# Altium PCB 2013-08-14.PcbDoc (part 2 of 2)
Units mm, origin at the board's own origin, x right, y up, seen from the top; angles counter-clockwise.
Board outline 30.96 x 91.67 mm, 2 copper layers (Top Layer, Bottom Layer); 88 components, 66 nets, 245 pads, 39 vias.
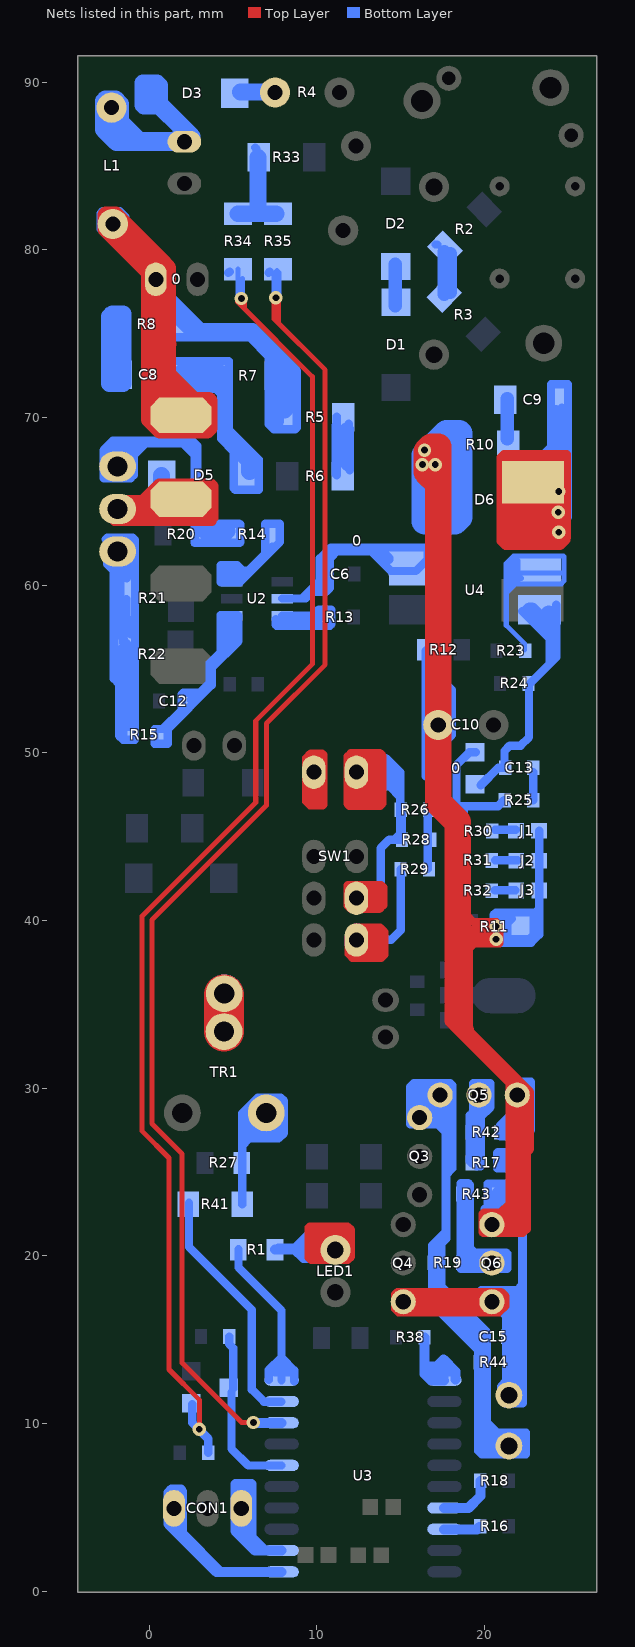
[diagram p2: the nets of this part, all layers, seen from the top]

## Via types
v1: diameter 0.8, hole 0.4, Top Layer to Bottom Layer, 36 vias
v2: diameter 1.27, hole 0.8, Top Layer to Bottom Layer, 3 vias

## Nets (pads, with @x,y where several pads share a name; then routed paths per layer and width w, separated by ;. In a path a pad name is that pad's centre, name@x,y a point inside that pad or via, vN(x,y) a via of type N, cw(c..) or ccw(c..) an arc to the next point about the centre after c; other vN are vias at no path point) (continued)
NewNet16: C15.1 pad.1@21.463,8.661 Q3.C Q5.C R19.1 R44.1 | length 80.4
  Bottom Layer w0.5: 17.95,30.308 18.079,30.179 18.079,25.209 17.723,24.853 17.723,21.028 17.432,20.737 17.432,18.171 20.149,15.454 20.149,10.065 20.224,9.99 20.753,9.461 22.477,9.461 22.477,8.157 19.847,8.157 19.642,8.362 19.642,14.355 16.893,17.104 16.893,20.639 17.68,21.426 17.68,27.398 17.228,27.85 15.568,27.85 15.568,30.083 15.793,30.308 17.96,30.308
  Bottom Layer w1: 16.57,29.252 16.57,28.616 16.85,28.336 16.375,28.336 16.171,28.54 16.171,29.597 16.085,29.683 Q5.C@17.303,29.683 ; 17.179,20.413 17.179,17.605 19.895,14.889 19.895,9.661 20.666,8.89 pad.1@21.464,8.89 ; Q5.C@17.411,29.759 17.411,28.324 17.82,27.915 ; 20.106,9.559 20.106,8.76 20.407,8.459 pad.1@22.024,8.459 ; 20.537,9.149 pad.1@22.089,9.149
NewNet17: Q6.B R19.2 R43.1 | length 23.3
  Bottom Layer w0.5: R43.1@18.731,24.013 18.731,19.896 19.087,19.54 Q6.B@20.407,19.54 ; 18.931,20.435 18.931,20.17 19.362,19.739 Q6.B@20.359,19.739 ; R19.2@18.585,19.222 18.585,24.331 19.038,24.331 19.135,24.234 19.135,20.478 19.421,20.192 21.308,20.192 21.356,20.144 21.356,19.222 R19.2@18.585,19.222
NewNet18: C15.2 pad.2 Q4.C Q6.C R17.2 R44.2 | length 67.4
  Top Layer w0.5: Q4.C@14.687,16.83 14.877,16.64 20.873,16.64 21.241,17.008 21.241,17.6 21.004,17.837 14.817,17.837 14.687,17.707 Q4.C@14.687,16.83
  Top Layer w1: Q4.C@15.291,17.268 Q6.C@20.649,17.268
  Bottom Layer w0.5: 20.764,26.149 20.764,25.231 21.863,25.231 22.24,24.854 22.24,18.246 21.939,17.945 19.805,17.945 19.696,17.836 19.696,17.093 20.019,16.77 20.935,16.77 21.302,16.403 21.302,12.522 20.989,12.209 20.989,11.478 21.25,11.217 22.282,11.217 22.282,26.17 20.785,26.17 R17.2@20.785,25.544
  Bottom Layer w1: Q6.C@20.612,17.557 21.658,16.511 21.658,16.403 ; Q6.C@20.725,17.4 21.814,17.4 21.776,17.362 pad.2@21.776,11.542 ; 21.415,25.679 21.954,25.679
NewNet19: Q5.B R17.1 R42.1 | length 16.6
  Bottom Layer w0.5: R17.1@19.253,25.527 19.135,25.645 19.135,28.384 19.329,28.578 19.329,30.287 20.353,30.287 20.353,28.859 19.771,28.277 19.771,25.43 19.771,25.35 R17.1@19.534,25.35 ; R17.1@19.367,25.646 19.367,28.266 19.895,28.794 Q5.B@19.895,30.034 ; Q5.B@19.588,28.918 Q5.B@19.588,29.602
NewNet20: R38.2 U3.11 | length 13.6
  Bottom Layer w0.254: U3.11@16.721,12.554 16.721,12.665 17.605,13.549 U3.11@18.489,12.665 ; 17.163,12.925 18.126,12.925 ; 17.226,13.044 18.039,13.044 ; 17.371,13.234 17.783,13.234 17.832,13.185
  Bottom Layer w0.6: R38.2@16.434,15.138 16.434,12.956 16.817,12.573 U3.11@17.602,12.573 ; 16.483,13.386 17.321,13.386 17.369,13.338 ; 16.51,13.512 16.636,13.386 16.832,13.386 ; 16.591,12.799 16.591,12.84 17.567,13.816 ; U3.11@17.567,12.732 17.567,13.816 ; U3.11@18.276,12.623 18.276,13.107 17.567,13.816
NewNet21: R16.1 U3.18 | length 2.2
  Bottom Layer w0.6: U3.18@17.602,3.683 19.549,3.683 R16.1@19.706,3.84
NewNet22: R18.1 U3.17 | length 3.4
  Bottom Layer w0.6: U3.17@17.602,4.953 19.041,4.953 19.761,5.673 R18.1@19.761,6.579
NewNet23: CON1.1 U3.2 | length 15.3
  Bottom Layer w0.6: CON1.1@5.304,5.933 5.863,5.933 ; 5.467,3.727 CON1.1@5.467,4.859 ; 5.802,3.296 CON1.1@5.802,5.645 ; U3.2@6.91,2.413 6.093,3.23 6.093,6.378 5.144,6.378 5.144,3.587 6.318,2.413 U3.2@7.899,2.413
NewNet24: CON1.3 U3.1 | length 20
  Bottom Layer w0.6: 1.889,6.055 1.328,6.055 1.156,5.883 1.156,3.996 4.009,1.143 7.899,1.143 4.257,1.143 1.975,3.425 1.975,5.947
NewNet25: pad.89 pad.138 U3.6 | length 10
  Bottom Layer w0.5: pad.138@4.775,15.189 4.775,14.746 5.015,14.506 pad.89@5.015,12.087 ; pad.89@4.918,11.854 4.918,8.491 5.916,7.493 U3.6@7.899,7.493
NewNet26: LED1.K R1.2 | length 28.1
  Top Layer w0.5: 9.721,21.749 11.836,21.749 12.026,21.559 12.026,19.941 11.842,19.757 9.662,19.757 9.525,19.894 9.525,21.689 9.585,21.749 9.949,21.749
  Top Layer w1: 10.088,21.298 10.088,20.255 10.147,20.196 11.404,20.196 11.582,20.374 11.582,21.262 11.534,21.31 10.609,21.31 ; LED1.K@10.657,20.682 LED1.K@11.155,20.682
  Bottom Layer w0.6: R1.2@7.518,20.371 8.711,20.371 9.208,19.874 11.773,19.874 11.913,20.014 11.913,20.941 11.589,21.265 9.531,21.265 8.711,20.445 R1.2@7.731,20.445 ; 9.175,20.467 LED1.K@11.601,20.467 ; 9.574,20.79 LED1.K@11.127,20.79
NewNet27: R1.1 U3.10 | length 18.8
  Bottom Layer w0.254: U3.10@7.018,12.554 7.018,12.665 7.941,13.588 7.941,13.478 ; U3.10@7.064,12.52 7.064,13.005 7.766,13.707 7.899,13.707 ; 7.46,12.925 8.423,12.925 ; 7.523,13.044 8.336,13.044 ; 7.863,13.588 U3.10@8.786,12.665
  Bottom Layer w0.5: R1.1@5.333,20.402 5.333,19.308 7.899,16.742 U3.10@7.899,12.573 ; U3.10@7.137,12.592 7.137,13.19 7.888,13.941 7.899,13.941 ; 7.899,13.799 7.899,14.103 ; 7.899,13.868 7.953,13.868 8.655,13.166 U3.10@8.655,12.512
NewNet28: R27.2 R41.1 TR1.G | length 18.1
  Bottom Layer w0.5: R41.1@5.563,23.063 5.563,28.506 6.491,29.435 7.85,29.435 8.033,29.252 8.033,27.312 7.72,26.999 5.963,26.999 5.563,26.598
  Bottom Layer w1: TR1.G@7.289,28.648 6.308,28.648 5.942,28.282 5.942,27.484 5.964,27.506 6.934,27.506 7.58,28.152 7.58,27.711 7.332,27.463
NewNet29: R41.2 U3.9 | length 14.7
  Bottom Layer w0.5: R41.2@2.379,23.162 2.379,20.526 6.13,16.775 6.13,12.022 6.847,11.305 U3.9@7.871,11.305
NewNet30: pad.252 R14.2 R20.1 | length 38.2
  Bottom Layer w0.5: pad.252@-2.494,67.833 -2.164,68.163 -0.868,68.163 ; pad.252@-1.92,67.043 -0.498,68.465 2.644,68.465 2.87,68.239 2.87,64.149 3.349,63.67 R14.2@5.381,63.67 ; pad.252@-1.656,66.385 -1.097,66.385 -0.919,66.563 -0.919,67.754 -0.208,68.465 ; pad.252@-1.427,66.385 -2.697,66.385 -2.722,66.41 -2.722,68.061 -2.164,68.62 2.561,68.62 2.87,68.311 2.87,67.782 ; 2.129,68.341 2.729,67.74 2.729,67.325 ; 2.729,67.875 2.729,62.543 2.745,62.527 5.403,62.527 5.435,62.559 R14.2@5.435,63.648
  Bottom Layer w1: R20.1@3.344,63.217 R14.2@4.648,63.217
NewNet31: R5.2 R6.2 | length 12
  Bottom Layer w0.5: R5.2@11.143,69.539 11.143,66.618 11.191,66.57 R5.2@11.191,70.062 ; R5.2@11.671,69.432 11.671,67.173 11.978,66.866 11.978,69.345 11.913,69.41 R5.2@11.913,69.625
NewNet32: C9.1 R10.2 | length 2.4
  Bottom Layer w0.8: R10.2@21.357,68.722 C9.1@21.357,71.135
NewNet33: 0.3@1.902,65.131 D5.1 pad.33 pad.251 | length 31.1
  Top Layer w0.5: pad.251@-2.327,64.045 -2.073,63.791 3.769,63.791 ; pad.251@-2.2,65.138 -0.422,65.138 0.566,66.125 3.712,66.125 3.901,65.936 3.901,64.003 3.748,63.85
  Top Layer w1: pad.251@-1.336,64.147 3.566,64.147 ; pad.251@-1.158,64.604 -0.93,64.833 0.3@1.814,64.833 ; 0.3@0.405,65.45 3.309,65.45 3.451,65.592 3.451,64.537 0.3@3.38,64.466
  Bottom Layer w1: pad.251@-2.073,64.884 -0.244,64.884 0.747,65.875 D5.1@0.747,66.56
NewNet34: D1.2 D2.2 | length 2.5
  Bottom Layer w0.8: D1.2@14.677,76.672 D2.2@14.677,79.136
NewNet35: D3.1 R4.1 | length 2.1
  Bottom Layer w1: D3.1@5.431,89.423 R4.1@7.488,89.423
NewNet36: R35.1 U3.8 | length 84.4
  Top Layer w0.3: v1@6.147,10.062 5.525,10.062 1.976,13.611 1.976,26.08 0.173,27.883 0.173,40.045 7.001,46.873 7.001,51.764 10.5,55.264 10.5,72.847 7.565,75.783 v1(7.565,77.154) ; v1@7.463,77.053 7.463,75.884 7.641,75.707 ; 7.717,75.707 v1@7.717,77.154
  Bottom Layer w0.3: R35.1@7.336,78.602 7.463,78.475 v1@7.463,77.154 ; v1(7.565,77.154) 7.565,78.704 R35.1@7.641,78.78 ; v1@7.742,77.231 R35.1@7.742,78.653
  Bottom Layer w0.6: v1@6.346,10.033 U3.8@7.899,10.033
  other v1: 6.223,10.058
NewNet37: pad.91 pad.140 R34.1 | length 82
  Top Layer w0.3: v1(2.997,9.652) 2.997,11.411 1.187,13.221 1.187,25.838 -0.413,27.438 -0.413,40.272 6.361,47.046 6.361,51.915 9.736,55.29 9.736,72.443 5.507,76.672 ; v1@5.279,77.104 5.279,76.9 5.507,76.672 ; v1(5.507,77.104) 5.507,76.672 ; 5.685,76.545 v1@5.685,76.926
  Bottom Layer w0.3: R34.1@5.304,78.856 5.304,77.332 5.533,77.104 v1@5.533,77.053 ; R34.1@5.583,78.297 5.583,77.256 v1@5.609,77.231
  Bottom Layer w0.5: pad.91@2.579,11.143 2.579,10.043 3.531,9.092 pad.140@3.531,8.255
NewNet38: R33.1 R34.2 R35.2 | length 5.4
  Bottom Layer w1: R34.2@5.304,82.158 R35.2@7.59,82.158 ; 6.498,82.387 R33.1@6.498,85.511
NewNet39: R2.1 R3.2 | length 4.8
  Bottom Layer w0.8: R3.2@17.598,77.358 R2.1@17.598,79.898 ; R3.2@17.979,77.485 R2.1@17.979,79.771
NewNet41: C8.1 R8.1 | length 9.8
  Bottom Layer w1: R8.1@-1.571,76.195 -2.199,76.195 -2.37,76.024 -2.37,72.035 -1.539,72.035 R8.1@-1.539,76.195
NewNet42: C8.2 D5.2 pad.32 R7.1 | length 32.5
  Bottom Layer w0.5: C8.2@1.145,71.722 3.959,71.722 4.287,71.394 4.287,68.747 5.042,67.992 5.042,65.787 5.133,65.696 6.529,65.696 6.529,67.502 4.74,69.291 4.74,73.376 1.145,73.376 C8.2@1.145,71.722
  Bottom Layer w1: C8.2@2.029,72.768 4.109,72.768 3.559,72.218 C8.2@2.244,72.218 ; 3.43,72.52 3.818,72.52 R7.1@4.497,71.841 ; 4.605,68.801 5.996,67.41 pad.32@5.996,66.764
NewNet43: 0.1@0.402,78.247 0.1@1.902,70.135 L1.1 R5.1 R7.2 R8.2 | length 143.9
  Top Layer w0.5: -0.176,69.782 0.387,69.219 3.588,69.219 3.824,69.455 3.824,70.973 ; -0.176,71.782 -0.176,79.74
  Top Layer w1: L1.1@-2.164,81.549 0.381,79.004 0.381,71.989 ; -0.081,79.161 0.021,79.059 0.021,69.89 0.656,69.255 3.45,69.255 3.577,69.382 3.577,71.008 ; 0.1@0.326,77.688 0.326,78.348 -2.57,81.244 -2.57,82.082 -2.011,82.082 0.91,79.161 ; 0.1@0.381,69.989 1.116,70.724 1.981,70.724 0.962,71.743 ; 0.58,71.465 0.63,71.414 0.1@0.63,70.627 ; 0.862,79.209 0.862,79.184 1.113,78.932 1.113,72.582 2.662,71.033 3.551,71.033 ; 0.962,73.743 0.962,74.537 1.128,74.371 ; 1.021,75.023 0.1@1.021,78.364 ; 0.1@1.128,70.866 1.128,72.371 ; 0.1@3.38,69.953 0.1@3.38,70.664
  Bottom Layer w0.5: L1.1@-2.214,81.549 -2.214,80.731 3.118,75.398 6.211,75.398 8.809,72.8 8.809,69.397 8.719,69.307 7.435,69.307 7.138,69.604 7.138,73.652 6.007,74.783 1.107,74.783 1.075,74.815 1.075,76.713 0.762,77.026 0.1@0.762,78.201 ; L1.1@-2.113,81.193 0.097,78.983 0.1@0.097,78.907 ; L1.1@-1.833,81.32 -1.503,81.32 0.859,78.958 0.1@0.859,77.561 ; 0.1@0.884,77.535 0.884,78.501 -1.427,80.812 -1.427,81.98 -1.757,82.311 -2.773,82.311 -2.9,82.184 -2.9,81.244 -0.106,78.45 -0.106,77.739 1.138,76.494 R8.2@1.138,75.884
  Bottom Layer w1: R8.2@1.479,76.335 2.68,75.134 6.055,75.134 7.85,73.339 7.85,71.194 ; 7.559,69.803 7.559,73.166 8.087,72.638 R5.1@8.087,70.45
NewNet44: 0.9 C9.2 D6.2 | length 88
  Top Layer w0.5: 20.968,62.956 20.968,67.63 21.158,67.82 24.915,67.82 24.915,62.826 ; 20.968,63.159 20.968,62.633 21.255,62.346 24.532,62.346 24.884,62.699 24.884,62.902 ; 21.23,62.727 24.557,62.727 ; 22.22,62.753 0.9@22.22,65.089
  Top Layer w1: 0.9@21.312,67.37 24.488,67.37 24.441,67.323 v1@24.441,63.083 ; 21.608,63.235 21.608,64.822 ; 22.473,63.271 23.54,63.271 ; 22.652,63.362 0.9@22.652,65.242 ; 0.9@23.465,65.191 23.541,65.115 23.541,63.388
  Bottom Layer w0.5: 21.572,66.553 21.572,66.683 21.76,66.871 24.115,66.871 ; 21.739,66.661 24.256,66.661 24.11,66.807 24.11,68.262 ; D6.2@22.067,66.279 22.067,66.332 23.974,68.238 ; 22.195,63.489 22.424,63.718 24.608,63.718 ; D6.2@23.7,63.945 24.881,63.945 24.983,64.047 24.983,71.998 23.973,71.998 23.973,68.188 ; D6.2@23.803,64.09 23.803,66.624 24.207,67.028 v1@24.207,64.085 ; 24.078,68.235 24.078,67.907 23.172,67.001 23.588,67.001 24.234,67.647 24.234,68.267 24.45,68.483 24.45,68.105 24.515,68.17 24.574,68.17 24.579,68.165 v1@24.579,64.128 ; 24.278,68.315 C9.2@24.278,70.5 ; 24.608,68.036 C9.2@24.608,70.601
  Bottom Layer w1: D6.2@21.814,63.997 21.814,63.21 21.941,63.083 24.354,63.083 24.675,63.404 24.675,63.963
  other v1: 24.435,63.151 24.409,64.345 24.435,65.589
NewNet45: R23.2 U4.1 | length 23.6
  Bottom Layer w0.3: 21.302,59.4 21.302,59.523 21.865,60.086 24.583,60.086 24.735,60.238 24.735,61.711 24.71,61.737 21.738,61.737 21.302,61.301 21.302,59.959 ; 21.357,59.832 21.357,59.882 21.89,60.416 U4.1@22.22,60.416 ; 21.484,60.365 21.56,60.365 ; 21.56,60.238 21.56,61.279 21.839,61.559 21.916,61.559 21.992,61.483 21.992,60.162 ; 21.763,60.314 21.763,61.279 21.839,61.356 ; R23.2@22.402,56.141 22.402,56.512 21.302,57.612 21.302,60.404 21.614,60.716 U4.1@24.578,60.716
NewNet46: R14.1 U2.6 | length 17.5
  Bottom Layer w0.5: 4.271,60.296 4.271,61.188 ; 4.299,60.811 4.387,60.811 ; 4.307,61.206 5.158,61.206 5.446,60.918 ; 4.454,61.206 5.247,61.206 5.446,61.008 U2.6@5.446,60.22 ; 6.923,61.773 6.923,63.67 7.801,63.67 7.801,62.576 5.397,60.172 4.271,60.172 4.271,60.857 5.905,60.857 7.338,62.29
  Bottom Layer w1: 4.605,60.544 5.289,60.544
NewNet47: C6.2 pad.4 U2.2 U4.4 | length 28.1
  Bottom Layer w0.5: U2.2@7.95,59.207 9.338,59.207 9.725,59.595 10.539,59.595 10.776,59.832 10.776,61.606 11.299,62.129 13.136,62.129 14.419,60.846 15.913,60.846 16.608,61.541 16.608,62.247 10.83,62.247 10.183,61.6 10.183,60.279 9.112,59.207 ; 10.038,59.843 10.22,59.843 10.598,60.221 ; C6.2@10.41,60.555 10.41,61.697 10.745,62.032 13.913,62.032 14.323,61.622 pad.4@14.323,61.53
NewNet48: R13.2 U2.3 | length 10.3
  Bottom Layer w0.5: U2.3@7.548,57.973 7.548,57.644 7.601,57.591 10.787,57.591 10.863,57.667 10.863,58.539 10.108,58.539 9.761,58.191 U2.3@7.95,58.191 ; 7.774,57.849 9.995,57.849 R13.2@10.302,58.156
NewNet49: pad.250 R15.1 R21.2 R22.2 | length 58.9
  Bottom Layer w0.5: pad.250@-2.582,62.741 -2.494,62.829 pad.250@-1.732,62.829 ; pad.250@-2.495,61.865 -2.495,61.256 -2.098,60.858 -2.098,54.432 -1.783,54.117 -1.783,51.018 -1.554,50.789 -0.843,50.789 -0.843,62.702 -0.97,62.829 -1.91,62.829 pad.250@-1.91,61.965 ; pad.250@-2.089,62.215 -2.089,55.414 -1.755,55.08 -1.755,51.565 -1.75,51.57 -1.021,51.57 ; R21.2@-1.808,58.485 -1.808,57.114 R22.2@-1.503,56.809 ; pad.250@-1.776,62.28 pad.250@-1.431,61.935 ; pad.250@-1.712,62.323 -1.712,57.902 -1.841,57.773 -1.841,58.679 -1.345,59.175 -1.345,57.472 ; R22.2@-1.668,55.311 -1.668,56.2 -1.323,56.545 -1.323,51.689 ; R22.2@-1.554,56.58 -1.554,57.596 ; -1.529,51.069 -1.529,51.831 ; pad.250@-1.376,61.737 -1.325,61.686 R21.2@-1.325,60.416 ; R22.2@-1.097,57.063 R21.2@-1.097,57.927
NewNet50: C12.1 R15.2 U2.4 | length 24
  Bottom Layer w0.5: C12.1@2.485,53.151 2.789,53.456 2.942,53.456 ; 2.586,53.583 3.018,53.583 3.628,54.193 3.628,55.361 4.644,56.377 ; 2.84,53.583 2.027,53.583 1.951,53.507 1.951,52.567 0.808,51.424 0.351,51.424 0.326,51.399 0.326,50.535 1.113,50.535 1.113,51.424 3.729,54.04 3.729,55.056 5.322,56.649 5.322,58.178 5.279,58.221 4.26,58.221 4.26,55.833
  Bottom Layer w1: 4.648,56.858 4.853,57.063 4.853,57.795
NewNet51: 0.3@17.206,49.072 C10.2 D6.1 J1.1 J2.1 J3.1 Q5.E Q6.E R10.1 R11.2 R12.2 R42.2 R43.2 | length 201.1
  Top Layer w0.5: 18.868,40.375 19.35,39.893 20.722,39.893 20.9,39.715 20.9,38.648 19.401,38.648 18.944,38.191 ; 19.122,39.435 v1@20.646,39.435 ; 19.172,39.029 v1@20.722,39.029 ; Q6.E@19.935,21.363 19.896,21.402 19.896,22.507 19.967,22.578 20.957,22.578 21.514,23.135 21.514,30.411 ; Q6.E@19.949,21.363 22.284,21.363 22.515,21.594 22.515,26.146 22.722,26.353 22.722,29.773 ; v1(20.696,39.664) 20.696,39.054 v1@20.9,38.851
  Top Layer w1: 18.131,35.752 18.131,34.025 Q5.E@22.449,29.707 ; 18.41,33.746 18.41,35.752 ; 18.614,38.902 18.817,38.699 18.817,33.365 ; 18.69,33.466 18.868,33.466 ; Q6.E@20.411,21.784 21.846,21.784 21.976,21.914 Q5.E@21.976,29.749 ; 21.348,22.045 21.739,22.436 21.834,22.436
  Top Layer w1.6: 17.191,66.131 16.556,66.766 16.556,67.985 16.836,68.264 17.242,68.264 17.242,47.055 18.41,45.887 18.41,35.752
  Bottom Layer w0.5: 16.485,53.462 17.044,52.902 17.044,50.272 ; R12.2@16.485,56.083 16.485,48.626 16.505,48.605 17.496,48.605 17.547,48.656 17.547,50.561 18.055,51.069 18.055,53.756 16.559,55.252 R12.2@16.559,55.952 ; 16.556,54.04 16.556,48.783 0.3@16.734,48.605 ; 16.742,54.002 16.742,54.831 ; 16.912,54.218 16.912,52.542 17.267,52.186 17.267,50.281 ; 0.3@16.963,49.367 16.963,50.408 17.064,50.51 ; 0.3@17.066,49.293 C10.2@17.066,52.298 ; 17.344,54.244 17.344,52.161 C10.2@17.369,52.135 ; C10.2@17.598,51.729 17.725,51.856 17.725,53.99 ; 20.203,22.855 20.203,24.316 21.355,24.316 21.399,24.272 21.399,21.615 21.27,21.486 20.245,21.486 20.025,21.706 20.025,22.807 20.424,23.206 ; Q6.E@20.715,22.045 20.715,23.831 20.86,23.976 20.86,23.248 20.364,22.752 20.364,21.739 20.418,21.685 21.157,21.685 21.205,21.637 21.205,24.164 ; 20.936,40 20.936,39.212 21.356,38.792 21.356,39.838 21.625,40.107 20.904,40.107 20.742,40.269 20.742,39.137 20.99,38.889 22.693,38.889 22.94,39.136 22.94,40.376 ; 22.768,30.308 22.768,27.484 22.423,27.139 20.946,27.139 20.946,27.786 21.647,28.487 21.647,30.384 22.779,30.384 ; 23.199,40.635 23.043,40.479 20.688,40.479 20.553,40.344 20.553,38.851 20.726,38.678 22.784,38.678 23.266,39.16 J1.1@23.266,45.364
  Bottom Layer w1: 21.96,27.981 21.528,27.549 22.294,27.549 22.369,27.624 Q5.E@22.369,29.78
  Bottom Layer w1.6: D6.1@17.447,65.112 17.447,68.343 R10.1@17.902,68.798 ; R10.1@17.674,68.976 17.928,68.976 18.004,69.052 R10.1@18.004,68.747 ; D6.1@16.455,63.819 18.233,63.819 18.487,64.073 18.487,69.052 17.75,69.052 16.455,67.756 D6.1@16.455,63.819
  other v1: 20.696,38.877 16.302,67.198 17.064,67.198 16.429,68.061
NewNet52: 0.2@19.441,48.132 C13.2 R24.2 U4.2 | length 19.4
  Bottom Layer w0.5: 0.2@19.782,48.071 20.821,49.11 C13.2@21.245,49.11 ; C13.2@21.114,49.183 21.2,49.269 21.2,50.115 21.513,50.428 22.164,50.428 22.661,50.925 22.661,54.075 24.293,55.707 U4.2@24.293,58.825 ; U4.2@22.251,58.453 23.9,56.804 23.9,55.387
  Bottom Layer w1: U4.2@22.709,58.469 22.822,58.469 23.835,57.456 U4.2@23.835,58.297
NewNet53: C13.1 R25.2 | length 1.7
  Bottom Layer w0.5: R25.2@22.911,47.168 C13.1@22.911,48.857
NewNet54: J1.2 R30.2 | length 1.2
  Bottom Layer w0.5: R30.2@20.634,45.41 J1.2@21.863,45.41
NewNet55: J2.2 R31.2 | length 1.3
  Bottom Layer w0.5: R31.2@20.634,43.594 J2.2@21.97,43.594
NewNet56: J3.2 R32.2 | length 1.2
  Bottom Layer w0.5: R32.2@20.612,41.815 J3.2@21.857,41.815
NewNet57: R26.1 R28.1 SW1.6 SW1.8 | length 57
  Top Layer w0.5: 11.842,49.793 11.842,46.961 11.949,46.854 13.786,46.854 13.916,46.984 13.916,49.836 13.763,49.989 12.038,49.989 ; 11.848,42.113 13.834,42.113 13.958,41.989 13.958,40.916 13.733,40.691 12.044,40.691 11.854,40.881 11.854,42.107
  Top Layer w1: SW1.8@12.186,49.627 13.502,49.627 13.561,49.568 13.561,47.376 13.513,47.328 12.34,47.328 SW1.8@12.34,49.188 ; SW1.6@12.53,41.177 13.407,41.177 13.478,41.248 13.478,41.651 13.466,41.663 SW1.6@12.589,41.663 ; 12.838,47.766 SW1.8@12.838,49.13
  Bottom Layer w0.5: SW1.8@12.213,48.732 14.575,48.732 14.677,48.63 14.677,48.402 ; SW1.8@12.34,48.376 14.55,48.376 14.905,48.021 14.905,47.563 ; SW1.6@12.365,41.366 13.508,41.366 13.813,41.671 13.813,44.312 14.318,44.818 R28.1@15.085,44.818 ; SW1.8@12.467,49.138 14.169,49.138 14.473,48.833 14.473,48.808 ; SW1.8@12.721,49.291 12.873,49.443 14.169,49.443 ; 14.626,44.818 14.651,44.818 14.981,45.148 14.981,47.386 14.372,47.995 12.01,47.995 11.908,48.097 11.908,49.621 11.984,49.697 14.118,49.697 14.981,48.833 R26.1@14.981,46.573 ; R28.1@15.079,45.066 R26.1@15.079,46.596
NewNet58: R29.1 SW1.5 | length 16.1
  Top Layer w0.5: SW1.5@11.913,39.008 11.913,38.001 12.127,37.787 13.857,37.787 14.035,37.965 14.035,39.316 13.774,39.577 SW1.5@12.316,39.577
  Top Layer w1: SW1.5@12.34,38.984 13.49,38.984 13.644,38.83 13.644,38.333 13.584,38.273 SW1.5@12.411,38.273
  Bottom Layer w0.5: SW1.5@12.37,38.843 14.44,38.843 15.007,39.41 R29.1@15.007,43.065
NewNet59: 0.1@19.441,50.037 R25.1 R26.2 R28.2 R29.2 R30.1 R31.1 R32.1 | length 17.2
  Bottom Layer w0.5: R29.2@16.62,43.071 R26.2@16.62,46.419 ; R26.2@16.785,46.624 16.985,46.824 17.902,46.824 ; 17.307,46.824 20.819,46.824 R25.1@21.173,47.178 ; 18.334,46.928 18.334,49.265 19.096,50.027 0.1@19.477,50.027 ; R32.1@18.771,42.005 18.771,46.799
NewNet60: ?.1@2.104,86.451 D3.2 L1.2 | length 26.8
  Bottom Layer w1: L1.2@-2.392,87.848 -1.478,86.933 -1.478,86.781 ; D3.2@0.529,88.813 ?.1@2.561,86.781 ; ?.1@1.621,86.527 -0.563,86.527 -1.706,87.67 -1.706,88.711 -2.011,89.016 -2.595,89.016 -2.722,88.889 -2.722,87.162 -1.96,86.4 ?.1@2.104,86.4 ; ?.1@1.9,86.603 1.9,87.289 0.605,88.584 -0.309,88.584 -0.36,88.635 -0.36,89.956 0.478,89.956 0.63,89.804 0.63,88.711 ?.1@2.459,86.883
NewNet61: SW1.1 | length 9.8
  Top Layer w0.5: 9.609,49.93 9.377,49.698 9.377,47.103 9.596,46.884 10.368,46.884 10.396,46.912 10.396,49.883 10.314,49.965 9.644,49.965
  Top Layer w1: 9.899,47.375 SW1.1@9.899,49.343
NewNet62: 
NewNet63: pad.1@4.481,35.641 TR1.T2 | length 4.1
  Top Layer w2.4: TR1.T2@4.47,33.376 pad.1@4.47,35.592
  Bottom Layer w2.3: TR1.T2@4.481,33.71 pad.1@4.481,35.641
pads on no net: U3.4 U3.7 U3.12 U3.13 U3.14 U3.15

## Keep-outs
Keep-Out Layer:
  circle w0.15: c11.176,31.013 r1.1
  circle w0.15: c11.176,76.886 r1.1
  lines w0.15: -4.191,86.614 -4.191,80.391 -0.686,20.269 -0.533,11.252 -0.686,2.311 0,2.311 0,0 22.2,0 22.2,2.311 22.911,2.311 22.758,11.252 22.86,17.932 26.619,82.55 26.619,86.614 ; -4.169,86.61 cw(c13.081,83.769) -2.591,91.516 25.045,91.516 ; 25.042,91.515 cw(c9.373,83.769) 26.619,86.614

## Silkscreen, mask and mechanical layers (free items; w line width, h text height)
Top Overlay:
  circle w0.2: c11.166,76.751 r2.5
  circle w0.2: c11.186,31.125 r2.5
  lines w0.2: -0.483,10.363 -0.025,10.363 ; 2.675,49.176 2.675,50.434 ; 5.088,49.227 5.088,50.434 ; 12.421,52.94 12.421,71.939 ; 14.108,33.045 15.24,33.045 ; 14.143,35.219 15.134,35.219 ; 14.808,50.197 23.063,50.197 ; 17.246,50.26 17.246,51.67 ; 17.339,23.288 cw(c16.256,25.857) 17.348,28.423 17.348,23.266 ; 19.355,0.254 19.355,2.134 21.971,2.134 ; 20.548,50.26 20.548,51.671 ; 3.404,52.94 21.412,52.94 21.412,71.939 3.404,71.939 3.404,52.94 ; 17.196,30.836 ccw(c19.761,29.743) 22.327,30.836 17.196,30.836
  text "H2" at 21.357,89.931 h0.8
  text "L" at 14.423,88.788 h1
  text "C2" at 5.609,85.943 h1 r270
  text "C3" at 5.202,79.212 h1 r270
  text "C1" at 12.086,72.735 h1
  text "N" at 24.735,72.455 h1
  text "1" at 1.467,71.917 h1 r270
  text "T1" at -1.656,70.902 h1 r270
  text "9" at 22.525,63.939 h1 r270
  text "4" at 1.507,53.336 h1 r270
  text "H1" at 1.9,35.524 h1 r270
  text "E" at 21.381,28.608 h1 r180
  text "C" at 18.845,28.559 h1 r180
  text "B" at 20.005,28.108 h1 r180
  text "C" at 15.224,26.768 h1 r90
  text "Q3" at 11.802,26.729 h1 r270
  text "Q5" at 19.263,26.191 h1 r270
  text "B" at 14.772,25.467 h1 r90
  text "T1" at 1.597,24.262 h0.8 r270
  text "E" at 15.204,24.146 h1 r90
  text "E" at 16.089,21.047 h1 r270
  text "E" at 21.351,21.047 h1 r270
  text "Q4" at 12.598,20.303 h1 r270
  text "B" at 16.527,19.756 h1 r270
  text "B" at 21.783,19.726 h1 r270
  text "C" at 16.06,18.552 h1 r270
  text "C" at 21.391,18.522 h1 r270
  text "94V-0" at 13.772,15.419 h1 r270
  text "2013-07-09" at 15.503,15.408 h1 r270
  text "RS-844-PC-V02" at 17.184,15.408 h1 r270
  text "-" at 21.113,13.519 h1 r270
  text "MOTOR1" at 19.243,12.462 h1 r270
  text "RoHS" at 13.756,9.973 h1 r270
  text "+" at 21.093,7.431 h1 r270
  text "3" at 1.05,2.299 h1 r270
  text "2" at 3.037,2.302 h1 r270
  text "1" at 5.048,2.269 h1 r270
Bottom Overlay:
  drawing of 182 lines, arcs and shapes, not listed
  text "H2" at 22.398,89.143 h1
  text "L" at 14.6,88.203 h1
  text "N" at 25.751,73.649 h1
  text "Q1" at 10.587,72.379 h1 r270
  text "G" at -1.351,68.112 h0.8 r270
  text "D" at -0.462,66.004 h0.8 r90
  text "S" at -1.275,62.956 h0.8 r270
  text "**" at 23.247,49.586 h1 r270
  text "U5" at 15.134,48.808 h1 r270
  text "**" at 2.339,39.251 h1 r270
  text "C13" at -0.486,39.181 h1 r180
  text "H1" at 4.023,37.426 h1 r270
  text "O" at 19.299,36.895 h0.8 r270
  text "G" at 19.02,33.785 h0.8 r270
  text "U1" at 19.122,31.346 h1 r270
  text "R27" at 3.294,28.095 h1 r180
  text "R37" at 2.577,17.376 h1 r180
  text "Q2" at 0.349,11.35 h1 r270
  text "-" at 19.835,11.226 h1 r270
  text "M" at 20.915,9.873 h1 r270
  text "+" at 19.02,7.988 h1 r270
  text "R36" at 4.666,7.165 h1 r270
  text "R18" at 19.071,5.692 h0.8 r180
Bottom Solder:
  lines w0.3: 4.358,60.213 4.358,60.879 ; 4.369,60.016 4.298,60.016 4.17,60.144 4.17,61.259 4.241,61.33 5.279,61.33 5.534,61.075 ; 4.376,60.975 4.376,61.131 ; 4.378,60.399 4.829,61.154 5.525,60.487 ; 4.419,60.89 4.419,60.961 4.611,61.153 5.122,61.153 5.371,60.904 5.371,60.762 ; 4.721,60.674 4.937,60.634 ; 4.809,60.87 5.241,60.576 ; 5.513,60.286 5.534,60.307 ; 5.534,60.307 5.534,61.075 ; 7.056,12.599 7.056,12.668 7.901,13.512 8.578,12.835 ; 7.362,60.394 7.362,60.84 7.366,60.844 ; 7.362,60.812 7.923,61.373 8.659,61.373 8.751,61.281 8.751,60.937 ; 7.366,60.761 7.459,60.913 ; 7.458,60.664 8.498,60.664 ; 7.508,60.939 8.419,60.939 ; 7.573,13.059 8.106,13.059 ; 7.784,13.198 7.801,13.215 8.046,13.215 ; 7.786,61.145 8.639,61.145 ; 8.431,59.998 8.557,59.998 ; 8.537,60.494 8.537,60.723 8.751,60.937 ; 8.537,60.519 8.61,60.519 8.751,60.66 8.751,60.937 ; 8.751,61.115 8.751,60.937 ; 16.759,12.599 16.759,12.668 17.604,13.512 18.281,12.835 ; 17.276,13.059 17.809,13.059 ; 17.487,13.198 17.504,13.215 17.749,13.215
  lines w0.4: 7.089,12.575 7.089,13.231 7.858,14 7.893,14 8.698,13.195 8.698,12.715 ; 7.281,13.091 7.395,13.091 7.946,13.642 ; 7.885,12.61 7.885,13.966 ; 8.482,60.026 8.658,60.026 8.7,60.068 8.7,60.332 ; 8.7,60.141 8.7,60.94 ; 16.693,12.601 16.693,13.095 17.527,13.929 17.585,13.929 18.375,13.139 18.375,12.715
